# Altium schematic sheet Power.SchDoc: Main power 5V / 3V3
size A4; Date: Not used; ApprovedBy: Not used; CheckedBy: Not used; Author: Not used; CompanyName: STMicroelectronics; DrawnBy: Not used; Engineer: Not used; Organization: Not used; Address1: Not used; Address2: Not used; Address3: Not used; Address4: Not used; DocumentNumber: 6; Revision: Not used; SheetNumber: 6; SheetTotal: 8
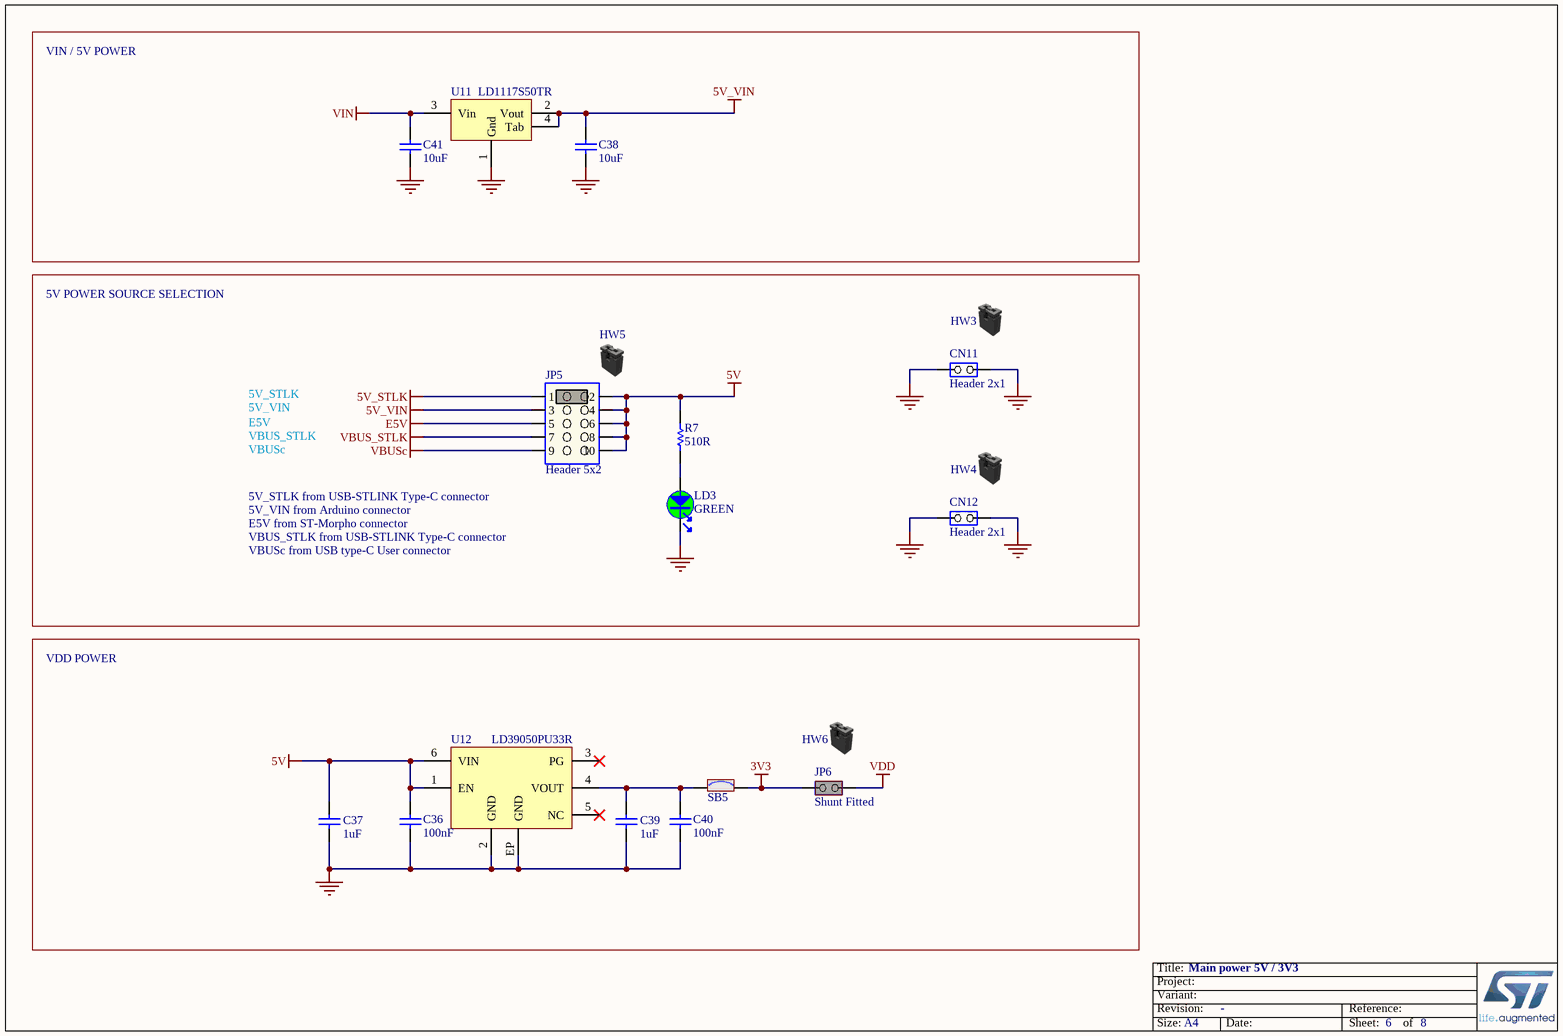
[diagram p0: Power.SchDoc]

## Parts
C36  value 100nF  [C0402]
C37  value 1uF  [C0603]
C38  value 10uF  [C0805]
C39  value 1uF  [C0603]
C40  value 100nF  [C0402]
C41  value 10uF  [C0805]
CN11  value Header 2x1  [CON_SAMTEC_TSW-102-09-X-S]  (hidden comment: Jumper_Header 2x1)
CN12  value Header 2x1  [CON_SAMTEC_TSW-102-09-X-S]  (hidden comment: Jumper_Header 2x1)
HW3  (no value)  (mechanical)
HW4  (no value)  (mechanical)
HW5  (no value)  (mechanical)
HW6  (no value)  (mechanical)
JP5  value Header 5x2  [CON_SAMTEC_TSW-105-07-X-D]  (hidden comment: Jumper_Header 5x2 Fitted 1-2)
JP6  Shunt Fitted  [CON_SAMTEC_TSW-102-07-G-S]
LD3  value GREEN  [LED_0603_OSRAM_LG-Q396-PS-35_GREEN_1A2K_H0P4]  (hidden comment: LED_green)
R7  value 510R  [R0603]
SB5  (no value)  [SOLDER-BRIDGE_R0603-0R]
U11  value LD1117S50TR  [REG_SOT223-TAB]
U12  value LD39050PU33R  [ICC_DFN6-EPAD_3X3_P095]

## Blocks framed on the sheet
VIN / 5V POWER: C38 C41 U11
VDD POWER: C36 C37 C39 C40 HW6 JP6 SB5 U12

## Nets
3V3: JP6.1(COMMON) SB5.2
5V: C36.2 C37.2 JP5.2 JP5.4 JP5.6 JP5.8 JP5.10 R7.2 U12.1(EN) U12.6(VIN)
5V_STLK: JP5.1
5V_VIN: C38.2 JP5.3 U11.2(Vout) U11.4(Tab)
E5V: JP5.5
GND: C36.1 C37.1 C38.1 C39.1 C40.1 C41.1 CN11.1(COMMON) CN11.2(NO) CN12.1(COMMON) CN12.2(NO) LD3.2 U11.1(Gnd) U12.2(GND) U12.EP(GND)
VBUS_STLK: JP5.7
VBUSc: JP5.9
VDD: JP6.2(NO)
VIN: C41.2 U11.3(Vin)
NetC39_2: C39.2 C40.2 SB5.1 U12.4(VOUT)
NetLD3_1: LD3.1 R7.1

Not connected (* = marked no-connect by the designer): U12 3(PG)* 5(NC)*

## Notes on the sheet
- 5V POWER SOURCE SELECTION
- 5V_STLK
- E5V
- 5V_VIN
- VBUS_STLK
- VBUSc
- 5V_VIN from Arduino connector
- 5V_STLK from USB-STLINK Type-C connector
- E5V from ST-Morpho connector
- VBUS_STLK from USB-STLINK Type-C connector
- VBUSc from USB type-C User connector

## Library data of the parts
C36 C40 = MCD-00102: Capacitor, MLCC, 100nF, 16V, X7R, 10%, 0402, T=0,5mm; Manufacturer_Part_Number: CC0402KRX7R7BB104; Manufacturer: YAGEO; Provided_By: Subcon; Initial_Board_Reference: MB1262
C37 C39 = MCD-00010: Capacitor, MLCC, 1uF, 16V, X5R, 10%, 0603, T=0,8mm; Manufacturer_Part_Number: CC0603KRX5R7BB105; Manufacturer: YAGEO; Provided_By: Subcon; Initial_Board_Reference: MB1274
C38 C41 = MCD-00014: Capacitor, MLCC, 10uF, 25V, X5R, 10%, 0805, T=0,85mm; Manufacturer_Part_Number: CC0805KRX5R8BB106; Manufacturer: YAGEO; ECCN_US: EAR99; ECCN_EU: NEC; Provided_By: SUBCO
CN11 CN12 = MCD-00214: Header, 2x1, 2.54mm, VR, TH, T=5.84mm/10.16mm; Part_Type: Connector; Part_Preference: Recommended; Manufacturer: SAMTEC; Manufacturer_Part_Number: TSW-102-09-G-S; Alternate_Internal_Part_Number: MCD-02393; Order_Code_RS: 180-3129; Component_Country_Of_Origin: China, Costa Rica, Malaysia, United States, Vietnam; ShowFields: YES; ID: 2652
HW3-HW6 = MCD-00043: SHUNT 2.54mm BLACK; Manufacturer_Part_Number: SNT-100-BK-G; Manufacturer: SAMTEC; Part_Type: Mechanical; Provided_By: Subcon; Initial_Board_Reference: MB1274
JP5 = MCD-01203: Header, 5x2, 2.54mm, VR, TH, T=5.84mm/2.54mm; BMS_Part_Number: 9083523; Part_Type: Connector; Part_Preference: Recommended; Manufacturer: SAMTEC; Manufacturer_Part_Number: TSW-105-07-G-D; Alternate_Internal_Part_Number: MCD-02391; Order_Code_RS: 161-2267; Component_Country_Of_Origin: China, Costa Rica, Malaysia, United States, Vietnam; ShowFields: YES; ID: 3293
JP6 = MCD-00683: Header, 2x1, 2,54mm, VR, TH, Height 5.84mm/2.54mm - Shunt Fitted by default; Part_Type: Connector; Manufacturer_Part_Number: TSW-102-07-x-S; Manufacturer: SAMTEC; Provided_By: Subcon; Initial_Board_Reference: MB1331
LD3 = MCD-00588: LED Green, 0603 SMD, Forward Voltage Typ=2V, Max=2.5V; Part_Type: Display; Manufacturer_Part_Number: LG Q396-PS-35; Manufacturer: OSRAM OPTO SEMICONDUCTORS; Alternate_Manufacturer_Part_Number: VLMTG1300-GS08; Alternate_Manufacturer: VISHAY SEMICONDUCTOR OPTO DIVISION; Provided_By: SUBCO
R7 = MCD-00225: Resistor,510R,0603,1%,1/10W; Manufacturer_Part_Number: RC0603FR-07510RL; Manufacturer: YAGEO; ECCN_US: EAR99; ECCN_EU: NEC; Provided_By: SUBCO
SB5 = MCD-00071: Solder Bridge ON; Part_Type: Mechanical; Manufacturer_Part_Number: RC0603JR-070RL; Manufacturer: YAGEO; Provided_By: SUBCO
U11 = MCD-00088: IC REG LDO 5V 0.8A SOT223; Manufacturer: STMICROELECTRONICS; BMS_Part_Number: 9176133; ECCN_US: EAR99; ECCN_EU: NEC; Provided_By: SUBCO with ST control
U12 = MCD-00215: Low quiescent current and low noise voltage regulators; Manufacturer: STMICROELECTRONICS; Part_Type: IC; BMS_Part_Number: 9176126; ECCN_US: EAR99; ECCN_EU: NEC; Provided_By: SUBCO with ST control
